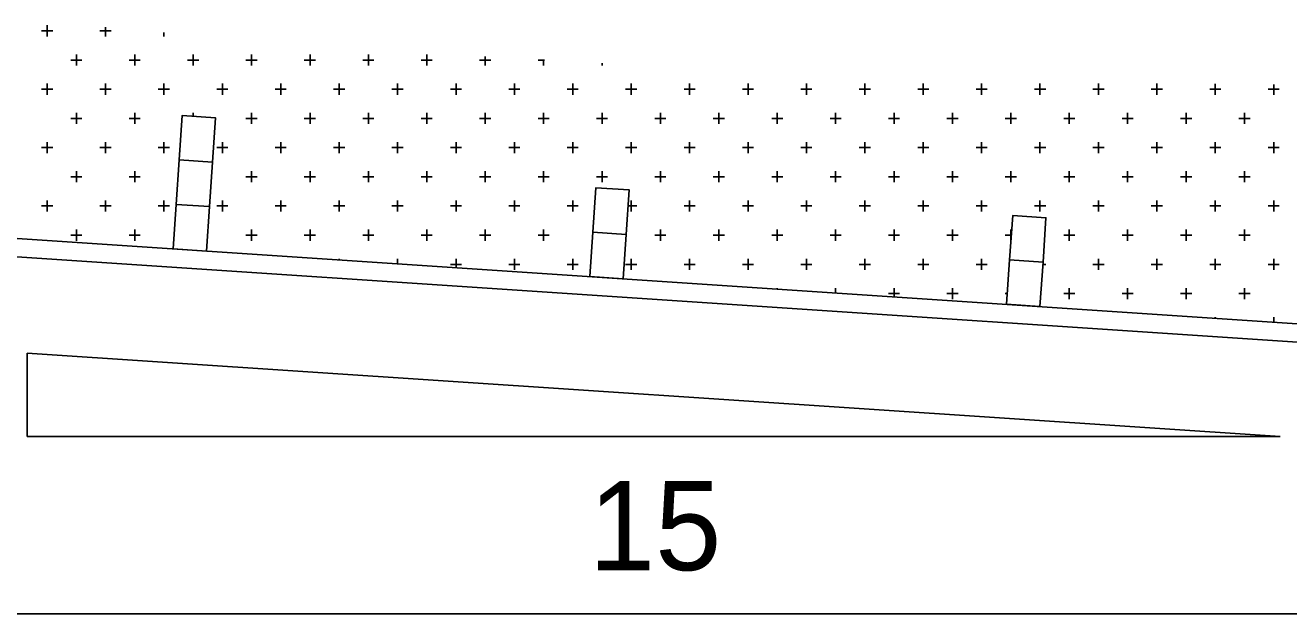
# Model space of a CAD drawing. Extents: x 1312564.5 to 1312581.5, y 1207298.4 to 1207309.4.
# Drawn here: x 1312567.489 to 1312568.534, y 1207301.635 to 1207302.122 of the extents above; entities that cross this region are included whole.
import ezdxf

# ---------------------------------------------------------------- set-up
doc = ezdxf.new("R2010")
doc.units = 0
for name, color, linetype in [('Level 15', 7, 'Continuous'), ('Level 2', 7, 'Continuous'), ('Level 3', 7, 'Continuous'), ('Level 4', 7, 'Continuous')]:
    doc.layers.add(name, color=color, linetype=linetype)

msp = doc.modelspace()

# ---------------------------------------------------------------- linework, layer by layer
at = {"layer": 'Level 15'}
for p, q in [((1312567.4902, 1207301.7817), (1312567.4902, 1207301.8508)), ((1312567.4902, 1207301.8508), (1312568.527, 1207301.7817)), ((1312568.527, 1207301.7817), (1312567.4902, 1207301.7817))]:
    msp.add_line(p, q, dxfattribs=at)
at = {"layer": 'Level 2'}
for p, q in [((1312566.9128, 1207301.9837), (1312570.1952, 1207301.7649)), ((1312570.1952, 1207301.7496), (1312566.9118, 1207301.9685))]:
    msp.add_line(p, q, dxfattribs=at)
for points in [[(1312567.616, 1207302.0107), (1312567.6436, 1207302.0089), (1312567.646, 1207302.0456), (1312567.6184, 1207302.0475)], [(1312567.6135, 1207301.9739), (1312567.6411, 1207301.9721), (1312567.6436, 1207302.0089), (1312567.616, 1207302.0107)], [(1312567.9584, 1207301.9509), (1312567.986, 1207301.9491), (1312567.9884, 1207301.9859), (1312567.9608, 1207301.9877)], [(1312567.6111, 1207301.9371), (1312567.6387, 1207301.9353), (1312567.6411, 1207301.9721), (1312567.6135, 1207301.9739)], [(1312568.3032, 1207301.9279), (1312568.3308, 1207301.9261), (1312568.3332, 1207301.9629), (1312568.3057, 1207301.9647)], [(1312567.9559, 1207301.9141), (1312567.9835, 1207301.9123), (1312567.986, 1207301.9491), (1312567.9584, 1207301.9509)], [(1312568.3007, 1207301.8912), (1312568.3283, 1207301.8893), (1312568.3308, 1207301.9261), (1312568.3032, 1207301.9279)]]:
    msp.add_lwpolyline(points, close=True, dxfattribs=at)
at = {"layer": 'Level 3'}
msp.add_line((1312570.1952, 1207301.6351), (1312565.7882, 1207301.6351), dxfattribs=at)
at = {"layer": 'Level 4'}
for p, q in [((1312567.5022, 1207302.1176), (1312567.5114, 1207302.1176)), ((1312567.5068, 1207302.113), (1312567.5068, 1207302.1222)), ((1312567.5505, 1207302.1176), (1312567.5597, 1207302.1176)), ((1312567.5551, 1207302.113), (1312567.5551, 1207302.1206)), ((1312567.6034, 1207302.113), (1312567.6034, 1207302.1161)), ((1312567.5263, 1207302.0934), (1312567.5356, 1207302.0934)), ((1312567.531, 1207302.0888), (1312567.531, 1207302.098)), ((1312567.5747, 1207302.0934), (1312567.5793, 1207302.0934)), ((1312567.5793, 1207302.0888), (1312567.5793, 1207302.098)), ((1312567.5793, 1207302.0934), (1312567.5839, 1207302.0934)), ((1312567.623, 1207302.0934), (1312567.6322, 1207302.0934)), ((1312567.6276, 1207302.0888), (1312567.6276, 1207302.098)), ((1312567.6713, 1207302.0934), (1312567.6805, 1207302.0934)), ((1312567.6759, 1207302.0888), (1312567.6759, 1207302.098)), ((1312567.7196, 1207302.0934), (1312567.7289, 1207302.0934)), ((1312567.7243, 1207302.0888), (1312567.7243, 1207302.098)), ((1312567.768, 1207302.0934), (1312567.7772, 1207302.0934)), ((1312567.7726, 1207302.0888), (1312567.7726, 1207302.098)), ((1312567.8163, 1207302.0934), (1312567.8255, 1207302.0934)), ((1312567.8209, 1207302.0888), (1312567.8209, 1207302.098)), ((1312567.8646, 1207302.0934), (1312567.8692, 1207302.0934)), ((1312567.8692, 1207302.0888), (1312567.8692, 1207302.0963)), ((1312567.8692, 1207302.0934), (1312567.8738, 1207302.0934)), ((1312567.913, 1207302.0934), (1312567.9182, 1207302.0934)), ((1312567.9176, 1207302.0888), (1312567.9176, 1207302.0935)), ((1312567.9659, 1207302.0888), (1312567.9659, 1207302.0908)), ((1312567.5068, 1207302.0647), (1312567.5068, 1207302.0739)), ((1312567.5551, 1207302.0647), (1312567.5551, 1207302.0739)), ((1312567.6034, 1207302.0647), (1312567.6034, 1207302.0739)), ((1312567.6518, 1207302.0647), (1312567.6518, 1207302.0739)), ((1312567.7001, 1207302.0647), (1312567.7001, 1207302.0739)), ((1312567.7484, 1207302.0647), (1312567.7484, 1207302.0739)), ((1312567.7967, 1207302.0647), (1312567.7967, 1207302.0739)), ((1312567.8451, 1207302.0647), (1312567.8451, 1207302.0739)), ((1312567.8934, 1207302.0647), (1312567.8934, 1207302.0739)), ((1312567.9417, 1207302.0647), (1312567.9417, 1207302.0739)), ((1312567.9901, 1207302.0647), (1312567.9901, 1207302.0739)), ((1312568.0384, 1207302.0647), (1312568.0384, 1207302.0739)), ((1312568.0867, 1207302.0647), (1312568.0867, 1207302.0739)), ((1312568.135, 1207302.0647), (1312568.135, 1207302.0739)), ((1312568.1834, 1207302.0647), (1312568.1834, 1207302.0739)), ((1312568.2317, 1207302.0647), (1312568.2317, 1207302.0739)), ((1312568.28, 1207302.0647), (1312568.28, 1207302.0739)), ((1312568.3283, 1207302.0647), (1312568.3283, 1207302.0739)), ((1312568.3767, 1207302.0647), (1312568.3767, 1207302.0739)), ((1312568.425, 1207302.0647), (1312568.425, 1207302.0739)), ((1312568.4733, 1207302.0647), (1312568.4733, 1207302.0737)), ((1312568.5217, 1207302.0647), (1312568.5217, 1207302.0731)), ((1312567.5022, 1207302.0693), (1312567.5114, 1207302.0693)), ((1312567.5505, 1207302.0693), (1312567.5597, 1207302.0693)), ((1312567.5988, 1207302.0693), (1312567.608, 1207302.0693)), ((1312567.6472, 1207302.0693), (1312567.6564, 1207302.0693)), ((1312567.6955, 1207302.0693), (1312567.7047, 1207302.0693)), ((1312567.7438, 1207302.0693), (1312567.753, 1207302.0693)), ((1312567.7921, 1207302.0693), (1312567.8014, 1207302.0693)), ((1312567.8405, 1207302.0693), (1312567.8497, 1207302.0693)), ((1312567.8888, 1207302.0693), (1312567.898, 1207302.0693)), ((1312567.9371, 1207302.0693), (1312567.9463, 1207302.0693)), ((1312567.9854, 1207302.0693), (1312567.9947, 1207302.0693)), ((1312568.0338, 1207302.0693), (1312568.043, 1207302.0693)), ((1312568.0821, 1207302.0693), (1312568.0913, 1207302.0693)), ((1312568.1304, 1207302.0693), (1312568.1396, 1207302.0693)), ((1312568.1788, 1207302.0693), (1312568.188, 1207302.0693)), ((1312568.2271, 1207302.0693), (1312568.2363, 1207302.0693)), ((1312568.2754, 1207302.0693), (1312568.2846, 1207302.0693)), ((1312568.3237, 1207302.0693), (1312568.333, 1207302.0693)), ((1312568.3721, 1207302.0693), (1312568.3813, 1207302.0693)), ((1312568.4204, 1207302.0693), (1312568.4296, 1207302.0693)), ((1312568.4687, 1207302.0693), (1312568.4779, 1207302.0693)), ((1312568.517, 1207302.0693), (1312568.5263, 1207302.0693)), ((1312567.5263, 1207302.0451), (1312567.5356, 1207302.0451)), ((1312567.531, 1207302.0405), (1312567.531, 1207302.0497)), ((1312567.5747, 1207302.0451), (1312567.5793, 1207302.0451)), ((1312567.5793, 1207302.0405), (1312567.5793, 1207302.0497)), ((1312567.5793, 1207302.0451), (1312567.5839, 1207302.0451)), ((1312567.6276, 1207302.0469), (1312567.6276, 1207302.0497)), ((1312567.6713, 1207302.0451), (1312567.6805, 1207302.0451)), ((1312567.6759, 1207302.0405), (1312567.6759, 1207302.0497)), ((1312567.7196, 1207302.0451), (1312567.7289, 1207302.0451)), ((1312567.7243, 1207302.0405), (1312567.7243, 1207302.0497)), ((1312567.768, 1207302.0451), (1312567.7772, 1207302.0451)), ((1312567.7726, 1207302.0405), (1312567.7726, 1207302.0497)), ((1312567.8163, 1207302.0451), (1312567.8255, 1207302.0451)), ((1312567.8209, 1207302.0405), (1312567.8209, 1207302.0497)), ((1312567.8646, 1207302.0451), (1312567.8692, 1207302.0451)), ((1312567.8692, 1207302.0405), (1312567.8692, 1207302.0497)), ((1312567.8692, 1207302.0451), (1312567.8738, 1207302.0451)), ((1312567.913, 1207302.0451), (1312567.9222, 1207302.0451)), ((1312567.9176, 1207302.0405), (1312567.9176, 1207302.0497)), ((1312567.9613, 1207302.0451), (1312567.9705, 1207302.0451)), ((1312567.9659, 1207302.0405), (1312567.9659, 1207302.0497)), ((1312568.0096, 1207302.0451), (1312568.0188, 1207302.0451)), ((1312568.0142, 1207302.0405), (1312568.0142, 1207302.0497)), ((1312568.0579, 1207302.0451), (1312568.0672, 1207302.0451)), ((1312568.0625, 1207302.0405), (1312568.0625, 1207302.0497)), ((1312568.1063, 1207302.0451), (1312568.1155, 1207302.0451)), ((1312568.1109, 1207302.0405), (1312568.1109, 1207302.0497)), ((1312568.1546, 1207302.0451), (1312568.1592, 1207302.0451)), ((1312568.1592, 1207302.0405), (1312568.1592, 1207302.0497)), ((1312568.1592, 1207302.0451), (1312568.1638, 1207302.0451)), ((1312568.2029, 1207302.0451), (1312568.2121, 1207302.0451)), ((1312568.2075, 1207302.0405), (1312568.2075, 1207302.0497)), ((1312568.2512, 1207302.0451), (1312568.2605, 1207302.0451)), ((1312568.2559, 1207302.0405), (1312568.2559, 1207302.0497)), ((1312568.2996, 1207302.0451), (1312568.3088, 1207302.0451)), ((1312568.3042, 1207302.0405), (1312568.3042, 1207302.0497)), ((1312568.3479, 1207302.0451), (1312568.3571, 1207302.0451)), ((1312568.3525, 1207302.0405), (1312568.3525, 1207302.0497)), ((1312568.3962, 1207302.0451), (1312568.4054, 1207302.0451)), ((1312568.4008, 1207302.0405), (1312568.4008, 1207302.0497)), ((1312568.4446, 1207302.0451), (1312568.4492, 1207302.0451)), ((1312568.4492, 1207302.0405), (1312568.4492, 1207302.0497)), ((1312568.4492, 1207302.0451), (1312568.4538, 1207302.0451)), ((1312568.4929, 1207302.0451), (1312568.5021, 1207302.0451)), ((1312568.4975, 1207302.0405), (1312568.4975, 1207302.0497)), ((1312567.5022, 1207302.0209), (1312567.5114, 1207302.0209)), ((1312567.5068, 1207302.0163), (1312567.5068, 1207302.0255)), ((1312567.5505, 1207302.0209), (1312567.5597, 1207302.0209)), ((1312567.5551, 1207302.0163), (1312567.5551, 1207302.0255)), ((1312567.5988, 1207302.0209), (1312567.608, 1207302.0209)), ((1312567.6034, 1207302.0163), (1312567.6034, 1207302.0255)), ((1312567.6472, 1207302.0209), (1312567.6564, 1207302.0209)), ((1312567.6518, 1207302.0163), (1312567.6518, 1207302.0255)), ((1312567.6955, 1207302.0209), (1312567.7047, 1207302.0209)), ((1312567.7001, 1207302.0163), (1312567.7001, 1207302.0255)), ((1312567.7438, 1207302.0209), (1312567.753, 1207302.0209)), ((1312567.7484, 1207302.0163), (1312567.7484, 1207302.0255)), ((1312567.7921, 1207302.0209), (1312567.8014, 1207302.0209)), ((1312567.7967, 1207302.0163), (1312567.7967, 1207302.0255)), ((1312567.8405, 1207302.0209), (1312567.8497, 1207302.0209)), ((1312567.8451, 1207302.0163), (1312567.8451, 1207302.0255)), ((1312567.8888, 1207302.0209), (1312567.898, 1207302.0209)), ((1312567.8934, 1207302.0163), (1312567.8934, 1207302.0255)), ((1312567.9371, 1207302.0209), (1312567.9463, 1207302.0209)), ((1312567.9417, 1207302.0163), (1312567.9417, 1207302.0255)), ((1312567.9854, 1207302.0209), (1312567.9947, 1207302.0209)), ((1312567.9901, 1207302.0163), (1312567.9901, 1207302.0255)), ((1312568.0338, 1207302.0209), (1312568.043, 1207302.0209)), ((1312568.0384, 1207302.0163), (1312568.0384, 1207302.0255)), ((1312568.0821, 1207302.0209), (1312568.0913, 1207302.0209)), ((1312568.0867, 1207302.0163), (1312568.0867, 1207302.0255)), ((1312568.1304, 1207302.0209), (1312568.1396, 1207302.0209)), ((1312568.135, 1207302.0163), (1312568.135, 1207302.0255)), ((1312568.1788, 1207302.0209), (1312568.188, 1207302.0209)), ((1312568.1834, 1207302.0163), (1312568.1834, 1207302.0255)), ((1312568.2271, 1207302.0209), (1312568.2363, 1207302.0209)), ((1312568.2317, 1207302.0163), (1312568.2317, 1207302.0255)), ((1312568.2754, 1207302.0209), (1312568.2846, 1207302.0209)), ((1312568.28, 1207302.0163), (1312568.28, 1207302.0255)), ((1312568.3237, 1207302.0209), (1312568.333, 1207302.0209)), ((1312568.3283, 1207302.0163), (1312568.3283, 1207302.0255)), ((1312568.3721, 1207302.0209), (1312568.3813, 1207302.0209)), ((1312568.3767, 1207302.0163), (1312568.3767, 1207302.0255)), ((1312568.4204, 1207302.0209), (1312568.4296, 1207302.0209)), ((1312568.425, 1207302.0163), (1312568.425, 1207302.0255)), ((1312568.4687, 1207302.0209), (1312568.4779, 1207302.0209)), ((1312568.4733, 1207302.0163), (1312568.4733, 1207302.0255)), ((1312568.517, 1207302.0209), (1312568.5263, 1207302.0209)), ((1312568.5217, 1207302.0163), (1312568.5217, 1207302.0255)), ((1312567.531, 1207301.9968), (1312567.531, 1207302.0014)), ((1312567.5793, 1207301.9968), (1312567.5793, 1207302.0014)), ((1312567.6759, 1207301.9968), (1312567.6759, 1207302.0014)), ((1312567.7243, 1207301.9968), (1312567.7243, 1207302.0014)), ((1312567.7726, 1207301.9968), (1312567.7726, 1207302.0014)), ((1312567.8209, 1207301.9968), (1312567.8209, 1207302.0014)), ((1312567.8692, 1207301.9968), (1312567.8692, 1207302.0014)), ((1312567.9176, 1207301.9968), (1312567.9176, 1207302.0014)), ((1312567.9659, 1207301.9968), (1312567.9659, 1207302.0014)), ((1312568.0142, 1207301.9968), (1312568.0142, 1207302.0014)), ((1312568.0625, 1207301.9968), (1312568.0625, 1207302.0014)), ((1312568.1109, 1207301.9968), (1312568.1109, 1207302.0014)), ((1312568.1592, 1207301.9968), (1312568.1592, 1207302.0014)), ((1312568.2075, 1207301.9968), (1312568.2075, 1207302.0014)), ((1312568.2559, 1207301.9968), (1312568.2559, 1207302.0014)), ((1312568.3042, 1207301.9968), (1312568.3042, 1207302.0014)), ((1312568.3525, 1207301.9968), (1312568.3525, 1207302.0014)), ((1312568.4008, 1207301.9968), (1312568.4008, 1207302.0014)), ((1312568.4492, 1207301.9968), (1312568.4492, 1207302.0014)), ((1312568.4975, 1207301.9968), (1312568.4975, 1207302.0014)), ((1312567.5263, 1207301.9968), (1312567.5356, 1207301.9968)), ((1312567.531, 1207301.9922), (1312567.531, 1207301.9968)), ((1312567.5747, 1207301.9968), (1312567.5793, 1207301.9968)), ((1312567.5793, 1207301.9922), (1312567.5793, 1207301.9968)), ((1312567.5793, 1207301.9968), (1312567.5839, 1207301.9968)), ((1312567.6713, 1207301.9968), (1312567.6805, 1207301.9968)), ((1312567.6759, 1207301.9922), (1312567.6759, 1207301.9968)), ((1312567.7196, 1207301.9968), (1312567.7289, 1207301.9968)), ((1312567.7243, 1207301.9922), (1312567.7243, 1207301.9968)), ((1312567.768, 1207301.9968), (1312567.7772, 1207301.9968)), ((1312567.7726, 1207301.9922), (1312567.7726, 1207301.9968)), ((1312567.8163, 1207301.9968), (1312567.8255, 1207301.9968)), ((1312567.8209, 1207301.9922), (1312567.8209, 1207301.9968)), ((1312567.8646, 1207301.9968), (1312567.8692, 1207301.9968)), ((1312567.8692, 1207301.9922), (1312567.8692, 1207301.9968)), ((1312567.8692, 1207301.9968), (1312567.8738, 1207301.9968)), ((1312567.913, 1207301.9968), (1312567.9222, 1207301.9968)), ((1312567.9176, 1207301.9922), (1312567.9176, 1207301.9968)), ((1312567.9613, 1207301.9968), (1312567.9705, 1207301.9968)), ((1312567.9659, 1207301.9922), (1312567.9659, 1207301.9968)), ((1312568.0096, 1207301.9968), (1312568.0188, 1207301.9968)), ((1312568.0142, 1207301.9922), (1312568.0142, 1207301.9968)), ((1312568.0579, 1207301.9968), (1312568.0672, 1207301.9968)), ((1312568.0625, 1207301.9922), (1312568.0625, 1207301.9968)), ((1312568.1063, 1207301.9968), (1312568.1155, 1207301.9968)), ((1312568.1109, 1207301.9922), (1312568.1109, 1207301.9968)), ((1312568.1546, 1207301.9968), (1312568.1592, 1207301.9968)), ((1312568.1592, 1207301.9922), (1312568.1592, 1207301.9968)), ((1312568.1592, 1207301.9968), (1312568.1638, 1207301.9968)), ((1312568.2029, 1207301.9968), (1312568.2121, 1207301.9968)), ((1312568.2075, 1207301.9922), (1312568.2075, 1207301.9968)), ((1312568.2512, 1207301.9968), (1312568.2605, 1207301.9968)), ((1312568.2559, 1207301.9922), (1312568.2559, 1207301.9968)), ((1312568.2996, 1207301.9968), (1312568.3088, 1207301.9968)), ((1312568.3042, 1207301.9922), (1312568.3042, 1207301.9968)), ((1312568.3479, 1207301.9968), (1312568.3571, 1207301.9968)), ((1312568.3525, 1207301.9922), (1312568.3525, 1207301.9968)), ((1312568.3962, 1207301.9968), (1312568.4054, 1207301.9968)), ((1312568.4008, 1207301.9922), (1312568.4008, 1207301.9968)), ((1312568.4446, 1207301.9968), (1312568.4492, 1207301.9968)), ((1312568.4492, 1207301.9922), (1312568.4492, 1207301.9968)), ((1312568.4492, 1207301.9968), (1312568.4538, 1207301.9968)), ((1312568.4929, 1207301.9968), (1312568.5021, 1207301.9968)), ((1312568.4975, 1207301.9922), (1312568.4975, 1207301.9968)), ((1312567.5022, 1207301.9726), (1312567.5114, 1207301.9726)), ((1312567.5068, 1207301.968), (1312567.5068, 1207301.9772)), ((1312567.5505, 1207301.9726), (1312567.5597, 1207301.9726)), ((1312567.5551, 1207301.968), (1312567.5551, 1207301.9772)), ((1312567.5988, 1207301.9726), (1312567.608, 1207301.9726)), ((1312567.6034, 1207301.968), (1312567.6034, 1207301.9772)), ((1312567.6472, 1207301.9726), (1312567.6564, 1207301.9726)), ((1312567.6518, 1207301.968), (1312567.6518, 1207301.9772)), ((1312567.6955, 1207301.9726), (1312567.7047, 1207301.9726)), ((1312567.7001, 1207301.968), (1312567.7001, 1207301.9772)), ((1312567.7438, 1207301.9726), (1312567.753, 1207301.9726)), ((1312567.7484, 1207301.968), (1312567.7484, 1207301.9772)), ((1312567.7921, 1207301.9726), (1312567.8014, 1207301.9726)), ((1312567.7967, 1207301.968), (1312567.7967, 1207301.9772)), ((1312567.8405, 1207301.9726), (1312567.8497, 1207301.9726)), ((1312567.8451, 1207301.968), (1312567.8451, 1207301.9772)), ((1312567.8888, 1207301.9726), (1312567.898, 1207301.9726)), ((1312567.8934, 1207301.968), (1312567.8934, 1207301.9772)), ((1312567.9371, 1207301.9726), (1312567.9463, 1207301.9726)), ((1312567.9417, 1207301.968), (1312567.9417, 1207301.9772)), ((1312567.9875, 1207301.9726), (1312567.9947, 1207301.9726)), ((1312567.9901, 1207301.968), (1312567.9901, 1207301.9772)), ((1312568.0338, 1207301.9726), (1312568.043, 1207301.9726)), ((1312568.0384, 1207301.968), (1312568.0384, 1207301.9772)), ((1312568.0821, 1207301.9726), (1312568.0913, 1207301.9726)), ((1312568.0867, 1207301.968), (1312568.0867, 1207301.9772)), ((1312568.1304, 1207301.9726), (1312568.1396, 1207301.9726)), ((1312568.135, 1207301.968), (1312568.135, 1207301.9772)), ((1312568.1788, 1207301.9726), (1312568.188, 1207301.9726)), ((1312568.1834, 1207301.968), (1312568.1834, 1207301.9772)), ((1312568.2271, 1207301.9726), (1312568.2363, 1207301.9726)), ((1312568.2317, 1207301.968), (1312568.2317, 1207301.9772)), ((1312568.2754, 1207301.9726), (1312568.2846, 1207301.9726)), ((1312568.28, 1207301.968), (1312568.28, 1207301.9772)), ((1312568.3237, 1207301.9726), (1312568.333, 1207301.9726)), ((1312568.3283, 1207301.968), (1312568.3283, 1207301.9772)), ((1312568.3721, 1207301.9726), (1312568.3813, 1207301.9726)), ((1312568.3767, 1207301.968), (1312568.3767, 1207301.9772)), ((1312568.4204, 1207301.9726), (1312568.4296, 1207301.9726)), ((1312568.425, 1207301.968), (1312568.425, 1207301.9772)), ((1312568.4687, 1207301.9726), (1312568.4779, 1207301.9726)), ((1312568.4733, 1207301.968), (1312568.4733, 1207301.9772)), ((1312568.517, 1207301.9726), (1312568.5263, 1207301.9726)), ((1312568.5217, 1207301.968), (1312568.5217, 1207301.9772)), ((1312567.5263, 1207301.9484), (1312567.5356, 1207301.9484)), ((1312567.531, 1207301.9438), (1312567.531, 1207301.9531)), ((1312567.5747, 1207301.9484), (1312567.5793, 1207301.9484)), ((1312567.5793, 1207301.9438), (1312567.5793, 1207301.9531)), ((1312567.5793, 1207301.9484), (1312567.5839, 1207301.9484)), ((1312567.6713, 1207301.9484), (1312567.6805, 1207301.9484)), ((1312567.6759, 1207301.9438), (1312567.6759, 1207301.9531)), ((1312567.7196, 1207301.9484), (1312567.7289, 1207301.9484)), ((1312567.7243, 1207301.9438), (1312567.7243, 1207301.9531)), ((1312567.768, 1207301.9484), (1312567.7772, 1207301.9484)), ((1312567.7726, 1207301.9438), (1312567.7726, 1207301.9531)), ((1312567.8163, 1207301.9484), (1312567.8255, 1207301.9484)), ((1312567.8209, 1207301.9438), (1312567.8209, 1207301.9531)), ((1312567.8646, 1207301.9484), (1312567.8692, 1207301.9484)), ((1312567.8692, 1207301.9438), (1312567.8692, 1207301.9531)), ((1312567.8692, 1207301.9484), (1312567.8738, 1207301.9484)), ((1312567.913, 1207301.9484), (1312567.9222, 1207301.9484)), ((1312567.9176, 1207301.9438), (1312567.9176, 1207301.9531)), ((1312568.0096, 1207301.9484), (1312568.0188, 1207301.9484)), ((1312568.0142, 1207301.9438), (1312568.0142, 1207301.9531)), ((1312568.0579, 1207301.9484), (1312568.0672, 1207301.9484)), ((1312568.0625, 1207301.9438), (1312568.0625, 1207301.9531)), ((1312568.1063, 1207301.9484), (1312568.1155, 1207301.9484)), ((1312568.1109, 1207301.9438), (1312568.1109, 1207301.9531)), ((1312568.1546, 1207301.9484), (1312568.1592, 1207301.9484)), ((1312568.1592, 1207301.9438), (1312568.1592, 1207301.9531)), ((1312568.1592, 1207301.9484), (1312568.1638, 1207301.9484)), ((1312568.2029, 1207301.9484), (1312568.2121, 1207301.9484)), ((1312568.2075, 1207301.9438), (1312568.2075, 1207301.9531)), ((1312568.2512, 1207301.9484), (1312568.2605, 1207301.9484)), ((1312568.2559, 1207301.9438), (1312568.2559, 1207301.9531)), ((1312568.2996, 1207301.9484), (1312568.3046, 1207301.9484)), ((1312568.3042, 1207301.9438), (1312568.3042, 1207301.9531)), ((1312568.3479, 1207301.9484), (1312568.3571, 1207301.9484)), ((1312568.3525, 1207301.9438), (1312568.3525, 1207301.9531)), ((1312568.3962, 1207301.9484), (1312568.4054, 1207301.9484)), ((1312568.4008, 1207301.9438), (1312568.4008, 1207301.9531)), ((1312568.4446, 1207301.9484), (1312568.4492, 1207301.9484)), ((1312568.4492, 1207301.9438), (1312568.4492, 1207301.9531)), ((1312568.4492, 1207301.9484), (1312568.4538, 1207301.9484)), ((1312568.4929, 1207301.9484), (1312568.5021, 1207301.9484)), ((1312568.4975, 1207301.9438), (1312568.4975, 1207301.9531)), ((1312567.7484, 1207301.928), (1312567.7484, 1207301.9289)), ((1312567.7967, 1207301.9248), (1312567.7967, 1207301.9289)), ((1312567.8451, 1207301.9215), (1312567.8451, 1207301.9289)), ((1312567.8934, 1207301.9197), (1312567.8934, 1207301.9289)), ((1312567.9417, 1207301.9197), (1312567.9417, 1207301.9289)), ((1312567.9901, 1207301.9197), (1312567.9901, 1207301.9289)), ((1312568.0384, 1207301.9197), (1312568.0384, 1207301.9289)), ((1312568.0867, 1207301.9197), (1312568.0867, 1207301.9289)), ((1312568.135, 1207301.9197), (1312568.135, 1207301.9289)), ((1312568.1834, 1207301.9197), (1312568.1834, 1207301.9289)), ((1312568.2317, 1207301.9197), (1312568.2317, 1207301.9289)), ((1312568.28, 1207301.9197), (1312568.28, 1207301.9289)), ((1312568.3767, 1207301.9197), (1312568.3767, 1207301.9289)), ((1312568.425, 1207301.9197), (1312568.425, 1207301.9289)), ((1312568.4733, 1207301.9197), (1312568.4733, 1207301.9289)), ((1312568.5217, 1207301.9197), (1312568.5217, 1207301.9289)), ((1312567.8405, 1207301.9243), (1312567.8497, 1207301.9243)), ((1312567.8888, 1207301.9243), (1312567.898, 1207301.9243)), ((1312567.9371, 1207301.9243), (1312567.9463, 1207301.9243)), ((1312567.9854, 1207301.9243), (1312567.9947, 1207301.9243)), ((1312568.0338, 1207301.9243), (1312568.043, 1207301.9243)), ((1312568.0821, 1207301.9243), (1312568.0913, 1207301.9243)), ((1312568.1304, 1207301.9243), (1312568.1396, 1207301.9243)), ((1312568.1788, 1207301.9243), (1312568.188, 1207301.9243)), ((1312568.2271, 1207301.9243), (1312568.2363, 1207301.9243)), ((1312568.2754, 1207301.9243), (1312568.2846, 1207301.9243)), ((1312568.3307, 1207301.9243), (1312568.333, 1207301.9243)), ((1312568.3721, 1207301.9243), (1312568.3813, 1207301.9243)), ((1312568.4204, 1207301.9243), (1312568.4296, 1207301.9243)), ((1312568.4687, 1207301.9243), (1312568.4779, 1207301.9243)), ((1312568.517, 1207301.9243), (1312568.5263, 1207301.9243)), ((1312568.1109, 1207301.9038), (1312568.1109, 1207301.9047)), ((1312568.1592, 1207301.9006), (1312568.1592, 1207301.9047)), ((1312568.2075, 1207301.8974), (1312568.2075, 1207301.9047)), ((1312568.2559, 1207301.8955), (1312568.2559, 1207301.9047)), ((1312568.3525, 1207301.8955), (1312568.3525, 1207301.9047)), ((1312568.4008, 1207301.8955), (1312568.4008, 1207301.9047)), ((1312568.4492, 1207301.8955), (1312568.4492, 1207301.9047)), ((1312568.4975, 1207301.8955), (1312568.4975, 1207301.9047)), ((1312568.2029, 1207301.9001), (1312568.2121, 1207301.9001)), ((1312568.2512, 1207301.9001), (1312568.2605, 1207301.9001)), ((1312568.2996, 1207301.9001), (1312568.3013, 1207301.9001)), ((1312568.3479, 1207301.9001), (1312568.3571, 1207301.9001)), ((1312568.3962, 1207301.9001), (1312568.4054, 1207301.9001)), ((1312568.4446, 1207301.9001), (1312568.4492, 1207301.9001)), ((1312568.4492, 1207301.9001), (1312568.4538, 1207301.9001)), ((1312568.4929, 1207301.9001), (1312568.5021, 1207301.9001)), ((1312568.4733, 1207301.8797), (1312568.4733, 1207301.8806)), ((1312568.5217, 1207301.8764), (1312568.5217, 1207301.8806))]:
    msp.add_line(p, q, dxfattribs=at)

# ---------------------------------------------------------------- texts
at = {"layer": 'Level 15'}
msp.add_text('15', height=0.07373, dxfattribs=at).set_placement((1312567.955, 1207301.6711))

doc.saveas('drawing.dxf')
